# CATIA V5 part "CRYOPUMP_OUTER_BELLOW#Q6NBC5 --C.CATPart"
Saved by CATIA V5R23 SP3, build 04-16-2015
Part number: CRYOPUMP_OUTER_BELLOW#Q6NBBL
Revision: --C
Nomenclature: _
Description: CRYOPUMP_OUTER_BELLOW
Property "ID": "Q6NBBL"
Property "AT": "PD"
Property "REP": "CM"
Property "External Part ID": "_"
Property "PREF": "Y"
Property "LONG": "_"
Property "PBS 1": "24"
Property "PBS 2": "CR"
Property "PBS 3": "LC"
Property "DEPT": "_"
Property "DIVN": "_"
Property "GROUP": "_"
Property "UNIT": "_"
Property "PARTY": "_"
Property "RO": "IOKIK"
Property "RE": "SEKACHI"
Property "PRO": "---"
Property "Change Type": "Major"
Property "Maturity Level": "CD"
Property "Export Number": "_"
Property "Description Modification": "FDR Model"
Property "Description Documents": "_"
Property "BOM": "_"
Property "User In Enovia": "VAUQUEJ"
Property "Object Type": "_"
Property "CADENAS_ID": "_"
Property "Life Cycle Status": "Approved"
Material "X2CrNiMoN17-11-2 1.4406 (316L(N))": density 7950 kg/m3, Young's modulus 2e+11 Pa, Poisson ratio 0.3, thermal expansion 1.6e-05 1/K
Bounding box of the stored display mesh (mm): x 13090 to 13980, y -719.799 to 719.799, z -5112.799 to -3673.2
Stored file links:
  C:\Users\pandeym\Desktop\__TCPH\CRYOPUMP_OUTER_BELLOW#Q6NBC5 --C.CATPart
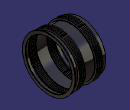
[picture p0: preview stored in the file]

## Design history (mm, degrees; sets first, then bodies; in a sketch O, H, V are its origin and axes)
Set1
  Sketch1 "CRYOPUMP_OUTER_BELLOW", origin (0, 0, 0), H (-1, 0, 0), V (0, 0, 1), geometry linked from another document
  Line1 "CRYOPUMP_CENTER_AXIS": linked copy from another document
  Sketch2 "OUTER_BELLOWS_RIGID_CYLINDER", origin (0, 0, 0), H (-1, 0, 0), V (0, 0, 1), geometry linked from another document
  Sketch3 "CRYOPUMP_BACK_FLANGE", origin (0, 0, 0), H (-1, 0, 0), V (0, 0, 1), geometry linked from another document
  Sketch4 "CRYOPUMP_FRONT_FLANGE", origin (0, 0, 0), H (1, 0, 0), V (0, 0, 1), geometry linked from another document
  Sketch5 "CRYOPUMP_BELLOWS_BACK_FLANGE_CYLINDERS", origin (0, 0, 0), H (-1, 0, 0), V (0, 0, 1), geometry linked from another document
Body1 (main body)
  Shaft1: profile Sketch1, axis Line1, angle 360, thin wall 0.75, second thickness 0.75
Body2
  Shaft2: profile Sketch2, axis axis of face of Shaft1, angle 360
Body3
  Sketch6 on zx-plane, origin (0, 0, 0), H (-1, 0, 0), V (0, 0, 1)
    projected line E1 (-13980, -3673) -> (-13980, -3753) from edge of Sketch3
    projected line E2 (-13960, -3673) -> (-13980, -3673) from edge of Sketch3
    point P3 (-13960, -3673)
    projected line E3 (-13960, -3753) -> (-13960, -3673) from edge of Sketch3
    projected line E4 (-13960, -3753) -> (-13960, -3736.5) from edge of Sketch3
    projected line E5 (-13960, -3721.5) -> (-13960, -3673) from edge of Sketch3
    point P5 (-13960, -3753)
    point P6 (-13960, -3673)
    projected line E6 (-13980, -3753) -> (-13960, -3753) from edge of Sketch3
    point P8 (-13960, -3753)
    projected line E7 (-13960, -3736.5) -> (-13860, -3736.5) from edge of Sketch5
    projected line E8 (-13860, -3736.5) -> (-13860, -3721.5) from edge of Sketch5
    projected line E9 (-13860, -3721.5) -> (-13960, -3721.5) from edge of Sketch5
    projected line E10 (-13090, -3721.5) -> (-13090, -3736.5) from edge of Sketch4
    projected line E11 (-13190, -3721.5) -> (-13090, -3721.5) from edge of Sketch4
    projected line E12 (-13190, -3736.5) -> (-13190, -3721.5) from edge of Sketch4
    projected line E13 (-13090, -3736.5) -> (-13190, -3736.5) from edge of Sketch4
    coincidence: P3 P6, P5 P8
  Shaft3: profile Sketch6, axis axis of face of Shaft2, angle 360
